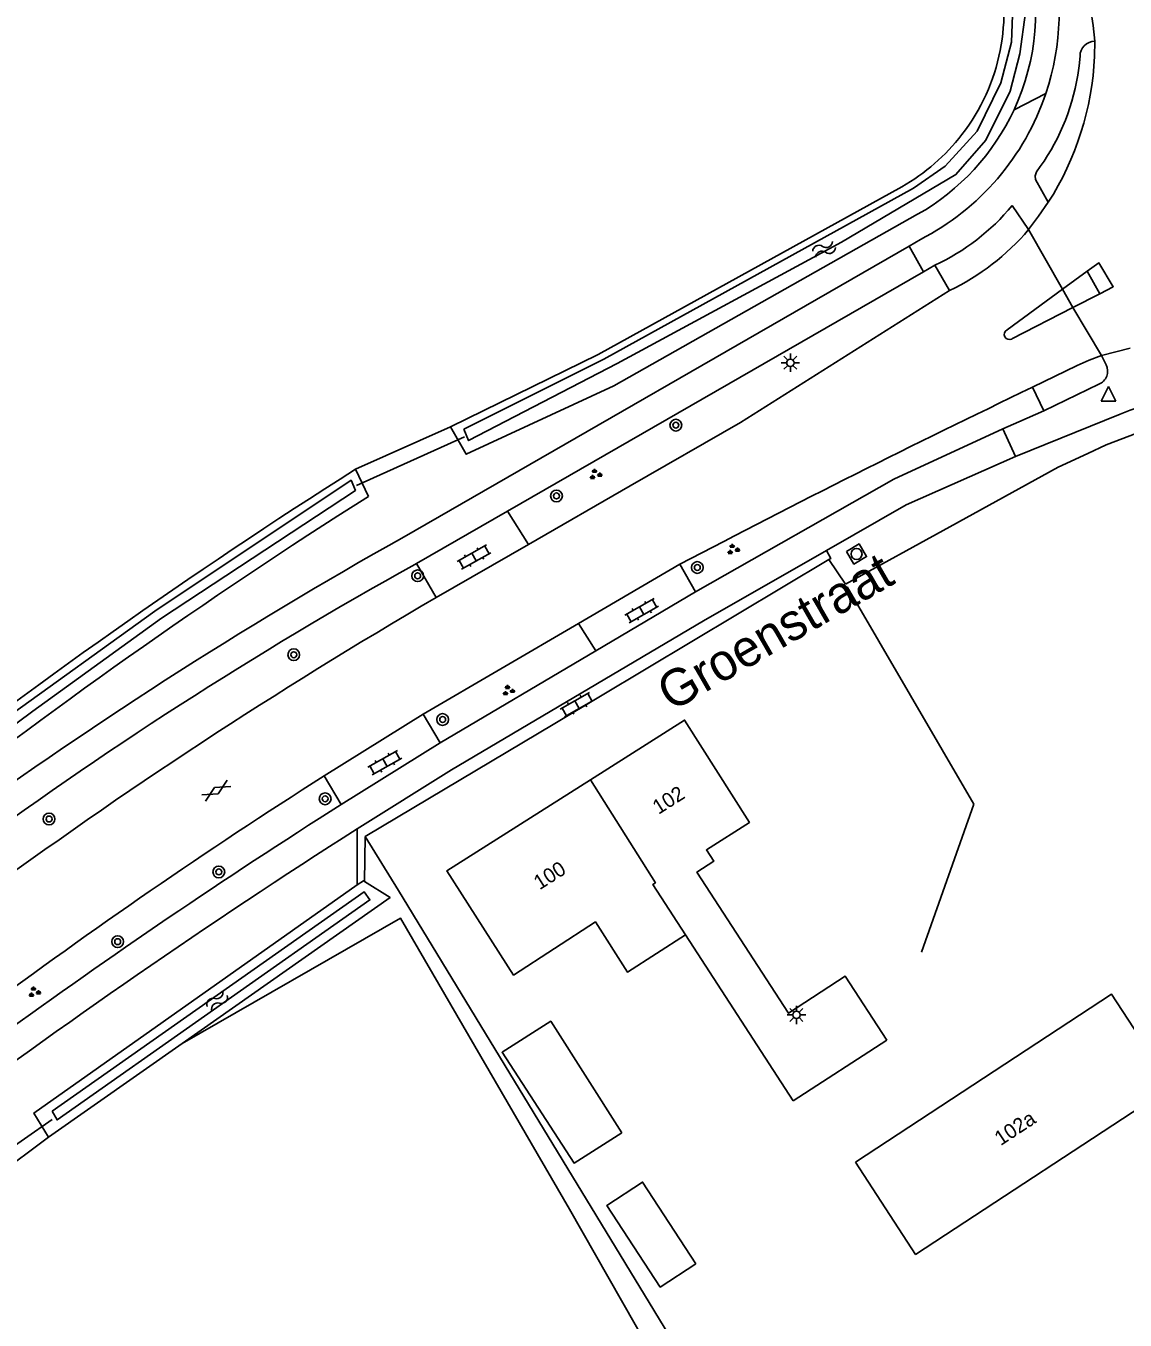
# Model space of a CAD drawing. Extents: x 137000 to 140001, y 403500 to 406000.
# Drawn here: x 139469.8 to 139544.4, y 403830.5 to 403918.5 of the extents above; entities that cross this region are included whole.
import ezdxf

# ---------------------------------------------------------------- set-up
doc = ezdxf.new("R2010")
doc.units = 0
for name, color, linetype in [('gg-afsc-erfafscheiding', 7, 'Continuous'), ('gg-afsc-hekwerk', 7, 'Continuous'), ('gg-anno-huisnummerreeks BGT', 7, 'Continuous'), ('gg-anno-openbare ruimte label', 7, 'Continuous'), ('gg-bbg-bijgebouw', 7, 'Continuous'), ('gg-bbg-hoofdgebouw', 7, 'Continuous'), ('gg-bbg-overig bouwwerk', 7, 'Continuous'), ('gg-bbg-tussenscheiding', 7, 'Continuous'), ('gg-knt-bronhoudergrens', 7, 'Continuous'), ('gg-knt-verharding', 7, 'Continuous'), ('gg-kntw-bovenkant insteek waterloop', 7, 'Continuous'), ('gg-kntw-waterlijn', 7, 'Continuous'), ('gg-kwrk-duiker nz buis', 7, 'Continuous'), ('gt-grn-groengrens', 7, 'Continuous'), ('gt-grn-weggrens', 7, 'Continuous'), ('gt-symb-boom', 7, 'Continuous'), ('gt-symb-gesloten verharding', 7, 'Continuous'), ('gt-symb-groenvak', 7, 'Continuous'), ('gt-symb-klinker verharding', 7, 'Continuous'), ('gt-symb-lichtmast', 7, 'Continuous'), ('gt-symb-rioolschacht', 7, 'Continuous'), ('gt-symb-waterafsluiter', 7, 'Continuous'), ('gt-symb-watersymbool', 7, 'Continuous')]:
    doc.layers.add(name, color=color, linetype=linetype)

# ---------------------------------------------------------------- blocks, each defined once
blk = doc.blocks.new('gt0-LMAST')
at = {"layer": 'gt-symb-lichtmast'}
for p, q in [((-0.182, 0.173), (-0.447, 0.438)), ((-0.005, 0.246), (-0.005, 0.621)), ((0.172, 0.173), (0.437, 0.438)), ((-0.255, -0.004), (-0.63, -0.004)), ((-0.182, -0.181), (-0.447, -0.446)), ((-0.005, -0.254), (-0.005, -0.629)), ((0.437, -0.446), (0.172, -0.181)), ((0.245, -0.004), (0.62, -0.004))]:
    blk.add_line(p, q, dxfattribs=at)
blk.add_circle((-0.005, -0.004), 0.25, dxfattribs=at)
blk = doc.blocks.new('gt0-WA')
at = {"layer": 'gt-symb-watersymbool'}
for centre, start, end in [((-0.323, 0.022), 28.07249, 151.92751), ((0.427, 0.422), 208.07248, 331.92751), ((-0.323, -0.428), 28.07249, 151.92751), ((0.427, -0.028), 208.07248, 331.92751)]:
    blk.add_arc(centre, 0.425, start, end, dxfattribs=at)
blk = doc.blocks.new('gt0-WAFSL')
at = {"layer": 'gt-symb-waterafsluiter'}
for p, q in [((-0.5, -0.333), (0, 0.667)), ((0, 0.667), (0.5, -0.333)), ((0.5, -0.333), (-0.5, -0.333))]:
    blk.add_line(p, q, dxfattribs=at)
blk = doc.blocks.new('gt0-RS')
at = {"layer": 'gt-symb-rioolschacht'}
blk.add_lwpolyline([(-0.5, -0.5), (0.5, -0.5), (0.5, 0.5), (-0.5, 0.5)], close=True, dxfattribs=at)
blk.add_circle((0, 0), 0.375, dxfattribs=at)
blk = doc.blocks.new('gt0-BOOM')
at = {"layer": 'gt-symb-boom'}
for radius in [0.4, 0.2]:
    blk.add_circle((0, 0), radius, dxfattribs=at)
blk = doc.blocks.new('gt0-GRVAK')
at = {"layer": 'gt-symb-groenvak'}
for p, q in [((-0.11, 0.189), (-0.228, 0.24)), ((-0.182, 0.153), (0.088, 0.153)), ((-0.091, 0.211), (-0.156, 0.322)), ((-0.047, 0.214), (-0.047, 0.393)), ((-0.004, 0.211), (0.061, 0.322)), ((0.015, 0.189), (0.133, 0.24)), ((0.262, -0.052), (0.197, 0.059)), ((0.305, -0.049), (0.305, 0.13)), ((0.349, -0.052), (0.414, 0.059)), ((-0.245, -0.228), (-0.363, -0.177)), ((-0.318, -0.264), (-0.047, -0.264)), ((-0.226, -0.206), (-0.291, -0.095)), ((-0.183, -0.203), (-0.183, -0.024)), ((-0.139, -0.206), (-0.074, -0.095)), ((-0.12, -0.228), (-0.002, -0.177)), ((0.243, -0.074), (0.125, -0.023)), ((0.17, -0.11), (0.441, -0.11)), ((0.368, -0.074), (0.486, -0.023))]:
    blk.add_line(p, q, dxfattribs=at)
blk = doc.blocks.new('gt0-KL1')
at = {"layer": 'gt-symb-klinker verharding'}
for p, q in [((-1.15, 0.3), (1.15, 0.3)), ((-1, -0.3), (-1, 0.3)), ((-0.5, 0.3), (-0.5, 0.45)), ((0, -0.3), (0, 0.3)), ((0.5, 0.3), (0.5, 0.45)), ((1, -0.3), (1, 0.3)), ((-1.15, -0.3), (1.15, -0.3)), ((-0.5, -0.45), (-0.5, -0.3)), ((0.5, -0.45), (0.5, -0.3))]:
    blk.add_line(p, q, dxfattribs=at)
blk = doc.blocks.new('gt0-GESVH1')
at = {"layer": 'gt-symb-gesloten verharding'}
for p, q in [((-0.992, -0.261), (0.008, 0.239)), ((0.008, -0.261), (-0.992, 0.239)), ((0.008, 0.239), (1.008, -0.261)), ((1.008, 0.239), (0.008, -0.261))]:
    blk.add_line(p, q, dxfattribs=at)

msp = doc.modelspace()

# ---------------------------------------------------------------- linework, layer by layer
at = {"layer": 'gg-afsc-erfafscheiding'}
msp.add_line((139525.444, 403880.565), (139524.321, 403882.228), dxfattribs=at)
for points in [[(139492.803, 403863.396), (139505.704, 403871.085), (139524.321, 403882.228)], [(139492.803, 403863.396), (139495.076, 403859.727), (139527.86, 403805.811)]]:
    msp.add_lwpolyline(points, dxfattribs=at)
at = {"layer": 'gg-afsc-hekwerk'}
for p, q in [((139541.911, 403889.445), (139539.896, 403888.496)), ((139539.896, 403888.496), (139532.529, 403884.453)), ((139525.568, 403880.381), (139534.16, 403865.612)), ((139534.16, 403865.612), (139530.61, 403855.542))]:
    msp.add_line(p, q, dxfattribs=at)
at = {"layer": 'gg-bbg-bijgebouw'}
msp.add_lwpolyline([(139510.255, 403843.274), (139507.01, 403841.206), (139502.111, 403848.741), (139505.423, 403850.849), (139510.255, 403843.274)], dxfattribs=at)
at = {"layer": 'gg-bbg-hoofdgebouw'}
for p, q in [((139521.9, 403845.447), (139514.581, 403856.726)), ((139528.255, 403849.57), (139521.9, 403845.447))]:
    msp.add_line(p, q, dxfattribs=at)
for points in [[(139528.255, 403849.57), (139525.435, 403853.9), (139521.585, 403851.395), (139515.348, 403860.985), (139516.491, 403861.725), (139516, 403862.492), (139518.919, 403864.356), (139514.51, 403871.321), (139508.115, 403867.262)], [(139508.115, 403867.262), (139498.36, 403861.072), (139502.898, 403853.981), (139508.451, 403857.599), (139510.623, 403854.186), (139514.581, 403856.726)], [(139526.12, 403841.261), (139543.524, 403852.681), (139547.616, 403846.416), (139530.212, 403834.996), (139526.12, 403841.261)]]:
    msp.add_lwpolyline(points, dxfattribs=at)
at = {"layer": 'gg-bbg-overig bouwwerk'}
msp.add_lwpolyline([(139515.284, 403834.359), (139511.661, 403839.916), (139509.232, 403838.333), (139512.854, 403832.775), (139515.284, 403834.359)], dxfattribs=at)
at = {"layer": 'gg-bbg-tussenscheiding'}
msp.add_lwpolyline([(139508.115, 403867.262), (139512.532, 403860.258), (139512.361, 403860.147), (139514.581, 403856.726)], dxfattribs=at)
at = {"layer": 'gg-knt-bronhoudergrens'}
msp.add_line((139536.901, 403912.803), (139539.063, 403913.911), dxfattribs=at)
msp.add_lwpolyline([(139517.373, 403819.285), (139506.683, 403838.078), (139495.201, 403857.856), (139480.373, 403849.343)], dxfattribs=at)
at = {"layer": 'gg-knt-verharding'}
for p, q in [((139542.386, 403917.462), (139542.367, 403916.409)), ((139537.881, 403904.651), (139536.766, 403906.285)), ((139495.455, 403883.769), (139529.764, 403903.535)), ((139529.764, 403903.535), (139530.541, 403903.982)), ((139502.476, 403885.522), (139530.739, 403901.791)), ((139531.519, 403902.23), (139530.739, 403901.791)), ((139531.519, 403902.23), (139532.519, 403900.508)), ((139540.186, 403900.604), (139541.859, 403901.836)), ((139541.859, 403901.836), (139542.72, 403900.294)), ((139518.313, 403891.548), (139532.519, 403900.508)), ((139540.186, 403900.604), (139536.425, 403897.842)), ((139540.186, 403900.604), (139540.9, 403899.358)), ((139542.72, 403900.294), (139540.9, 403899.358)), ((139540.9, 403899.358), (139536.75, 403897.218)), ((139544.782, 403896.599), (139542.835, 403896.103)), ((139542.835, 403896.103), (139543.166, 403895.457)), ((139538.149, 403893.937), (139538.921, 403892.332)), ((139542.666, 403894.14), (139538.921, 403892.332)), ((139544.11, 403892.12), (139536.992, 403889.228)), ((139538.921, 403892.332), (139537.231, 403891.585)), ((139510.81, 403887.229), (139518.313, 403891.548)), ((139537.231, 403891.585), (139536.13, 403891.112)), ((139536.13, 403891.112), (139528.727, 403887.701)), ((139536.992, 403889.228), (139529.577, 403885.94)), ((139528.727, 403887.701), (139515.262, 403880.027)), ((139503.91, 403883.258), (139510.81, 403887.229)), ((139529.577, 403885.94), (139524.155, 403882.845)), ((139502.476, 403885.522), (139496.293, 403881.961)), ((139503.91, 403883.258), (139502.476, 403885.522)), ((139497.627, 403879.642), (139503.91, 403883.258)), ((139496.19, 403881.902), (139496.293, 403881.961)), ((139496.293, 403881.961), (139497.627, 403879.642)), ((139507.312, 403877.887), (139514.199, 403881.914)), ((139514.199, 403881.914), (139515.262, 403880.027)), ((139515.262, 403880.027), (139508.489, 403876.029)), ((139507.312, 403877.887), (139496.747, 403871.709)), ((139508.489, 403876.029), (139507.312, 403877.887)), ((139508.489, 403876.029), (139497.9, 403869.78)), ((139490.015, 403867.521), (139496.747, 403871.709)), ((139497.9, 403869.78), (139496.747, 403871.709)), ((139497.9, 403869.78), (139491.17, 403865.583)), ((139490.015, 403867.521), (139491.17, 403865.583)), ((139492.274, 403860.111), (139492.269, 403863.924)), ((139492.803, 403863.396), (139492.757, 403860.354))]:
    msp.add_line(p, q, dxfattribs=at)
for points in [[(139542.107, 403919.569), (139542.277, 403918.52), (139542.386, 403917.462)], [(139541.381, 403916.43), (139541.318, 403915.783), (139541.227, 403915.139)], [(139539.222, 403906.51), (139538.352, 403908.063), (139538.336, 403908.319), (139538.416, 403908.57)], [(139539.222, 403906.51), (139538.568, 403905.569), (139537.881, 403904.651)], [(139541.859, 403901.836), (139542.666, 403902.39), (139543.638, 403900.767), (139542.72, 403900.294)], [(139542.835, 403896.103), (139542.009, 403895.774), (139541.194, 403895.41), (139538.149, 403893.937)], [(139524.155, 403882.845), (139515.79, 403878.071), (139498.68, 403867.942), (139492.269, 403863.924)], [(139524.155, 403882.845), (139524.452, 403882.305), (139524.321, 403882.228)]]:
    msp.add_lwpolyline(points, dxfattribs=at)
for centre, radius, start, end in [((139522.573, 403919.435), 17.39, 341.48074, 15.37683), ((139542.414, 403916.429), 1.033, 91.56613, 179.95267), ((139522.402, 403917.303), 19.985, 327.31267, 357.4363), ((139526.514, 403917.549), 14.909, 322.96878, 350.69722), ((139522.577, 403919.439), 17.388, 297.25921, 341.46221), ((139525.15, 403915.893), 15.075, 294.99176, 320.40356), ((139525.453, 403915.195), 16.298, 295.69368, 319.68993), ((139536.59, 403897.531), 0.352, 117.98795, 297.03605), ((139542.282, 403895.039), 0.978, 293.12977, 25.29162), ((139852.441, 403237.997), 727.349, 115.601281, 117.712404), ((139549.735, 403878.278), 14.941, 90.16686, 112.11323), ((139645.929, 403614.738), 308.253, 119.21901, 126.25818), ((139634.325, 403632.997), 284.666, 119.0291, 126.51838), ((139676.342, 403573.19), 354.757, 120.24966, 126.30435), ((139699.535, 403538.164), 390.352, 122.46246, 126.61859), ((139737.102, 403478.72), 458.416, 122.44451, 125.95613), ((139754.07, 403453.236), 487.037, 122.51629, 126.7364)]:
    msp.add_arc(centre, radius, start, end, dxfattribs=at)
at = {"layer": 'gg-kntw-bovenkant insteek waterloop'}
for p, q in [((139492.163, 403888.365), (139493.027, 403886.524)), ((139471.282, 403842.966), (139480.373, 403849.343))]:
    msp.add_line(p, q, dxfattribs=at)
for points in [[(139498.602, 403891.254), (139508.635, 403896.168), (139529.279, 403907.571)], [(139530.345, 403905.692), (139509.706, 403894.037), (139499.673, 403889.38), (139498.602, 403891.254)], [(139492.274, 403860.111), (139492.686, 403860.398), (139492.757, 403860.354)], [(139492.274, 403860.111), (139470.299, 403844.607), (139471.282, 403842.966)], [(139480.373, 403849.343), (139494.505, 403859.257), (139492.757, 403860.354)]]:
    msp.add_lwpolyline(points, dxfattribs=at)
for centre, radius, start, end in [((139522.521, 403919.481), 13.694, 322.31782, 15.23726), ((139522.52, 403919.48), 15.855, 335.09377, 15.23993), ((139522.522, 403919.482), 15.855, 299.56586, 335.08501), ((139522.52, 403919.484), 13.697, 299.56768, 322.30919), ((139700.674, 403558.82), 389.97, 122.32257, 128.1515), ((139700.649, 403558.844), 387.919, 122.35882, 128.15069)]:
    msp.add_arc(centre, radius, start, end, dxfattribs=at)
at = {"layer": 'gg-kntw-waterlijn'}
for points in [[(139499.504, 403891.098), (139509.028, 403895.843), (139530.077, 403907.471), (139532.22, 403908.973), (139534.394, 403911.337), (139535.998, 403914.628), (139536.734, 403917.389), (139536.827, 403919.832), (139536.592, 403922.537), (139535.83, 403925.194), (139533.453, 403931.96), (139534.163, 403932.21), (139537.266, 403923.375), (139537.684, 403919.4), (139537.295, 403916.598), (139536.631, 403914.072), (139534.981, 403910.73), (139532.952, 403908.396), (139525.185, 403903.794), (139509.939, 403895.554), (139499.831, 403890.319), (139499.504, 403891.098)], [(139444.088, 403853.309), (139453.931, 403860.579), (139468.26, 403871.342), (139478.509, 403878.713), (139491.852, 403887.622), (139492.151, 403886.928), (139478.974, 403878.248), (139470.232, 403871.927), (139444.473, 403852.754), (139444.088, 403853.309)], [(139471.533, 403844.731), (139492.733, 403859.653), (139493.126, 403859.095), (139471.876, 403844.138), (139471.533, 403844.731)]]:
    msp.add_lwpolyline(points, dxfattribs=at)
at = {"layer": 'gg-kwrk-duiker nz buis'}
for p, q in [((139499.564, 403890.563), (139492.21, 403887.261)), ((139471.545, 403844.179), (139464.929, 403839.563))]:
    msp.add_line(p, q, dxfattribs=at)
at = {"layer": 'gt-grn-groengrens'}
for p, q in [((139492.163, 403888.365), (139498.602, 403891.254)), ((139539.896, 403888.496), (139541.911, 403889.445)), ((139532.529, 403884.453), (139539.896, 403888.496)), ((139525.444, 403880.565), (139532.529, 403884.453)), ((139465.703, 403838.791), (139471.282, 403842.966))]:
    msp.add_line(p, q, dxfattribs=at)
msp.add_lwpolyline([(139541.911, 403889.445), (139543.159, 403890.032), (139546.191, 403891.184), (139550.032, 403891.773)], dxfattribs=at)
at = {"layer": 'gt-grn-weggrens'}
for p, q in [((139537.881, 403904.651), (139540.186, 403900.604)), ((139529.764, 403903.535), (139530.739, 403901.791)), ((139542.835, 403896.103), (139540.9, 403899.358)), ((139536.13, 403891.112), (139536.992, 403889.228))]:
    msp.add_line(p, q, dxfattribs=at)

# ---------------------------------------------------------------- block references
at = {"layer": 'gt-symb-boom'}
for p in [(139513.919, 403891.361), (139505.807, 403886.551), (139496.375, 403881.126), (139515.379, 403881.687), (139487.957, 403875.758), (139498.072, 403871.354), (139490.088, 403865.967), (139471.33, 403864.591), (139482.865, 403860.995), (139475.99, 403856.257)]:
    msp.add_blockref('gt0-BOOM', p, dxfattribs=at)
at = {"layer": 'gt-symb-gesloten verharding', "rotation": 30.59043540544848}
msp.add_blockref('gt0-GESVH1', (139482.685, 403866.525), dxfattribs=at)
at = {"layer": 'gt-symb-groenvak'}
for p in [(139508.445, 403888.007), (139517.801, 403882.913), (139502.523, 403873.317), (139470.312, 403852.822)]:
    msp.add_blockref('gt0-GRVAK', p, dxfattribs=at)
at = {"layer": 'gt-symb-klinker verharding'}
for p, rotation in [((139500.208, 403882.393), 29.282828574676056), ((139511.599, 403878.747), 29.282828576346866), ((139507.205, 403872.363), 29.25482150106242), ((139494.15, 403868.424), 29.282828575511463)]:
    msp.add_blockref('gt0-KL1', p, dxfattribs=dict(at, rotation=rotation))
at = {"layer": 'gt-symb-lichtmast'}
for p in [(139521.707, 403895.606), (139522.121, 403851.282)]:
    msp.add_blockref('gt0-LMAST', p, dxfattribs=at)
at = {"layer": 'gt-symb-rioolschacht', "rotation": -59.458901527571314}
msp.add_blockref('gt0-RS', (139526.198, 403882.609), dxfattribs=at)
at = {"layer": 'gt-symb-waterafsluiter'}
msp.add_blockref('gt0-WAFSL', (139543.326, 403893.315), dxfattribs=at)
at = {"layer": 'gt-symb-watersymbool'}
for p, rotation in [((139523.943, 403903.291), 26.56505117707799), ((139482.716, 403852.198), 45.16208097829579)]:
    msp.add_blockref('gt0-WA', p, dxfattribs=dict(at, rotation=rotation))

# ---------------------------------------------------------------- texts
at = {"layer": 'gg-anno-huisnummerreeks BGT'}
for s, rotation, p in [('102', 32.4, (139512.74, 403864.868)), ('100', 32.4, (139504.665, 403859.744)), ('102a', 33.3, (139535.991, 403842.356))]:
    msp.add_text(s, height=1, rotation=rotation, dxfattribs=at).set_placement(p)
at = {"layer": 'gg-anno-openbare ruimte label'}
msp.add_text('Groenstraat', height=2.5, rotation=29.9, dxfattribs=at).set_placement((139513.616, 403871.858))

doc.saveas('drawing.dxf')
